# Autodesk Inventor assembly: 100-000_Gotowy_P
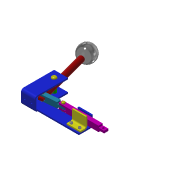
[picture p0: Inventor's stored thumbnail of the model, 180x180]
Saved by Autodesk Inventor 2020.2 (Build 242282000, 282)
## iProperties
Created: 2014-01
Part Number: 100-000_Gotowy_P
Document SubType Name: Assembly
Designer: F.Stasiak
Manager: www.cadconsulting.pl
Company: Fabian Stasiak CAD Consulting
Author: F.Stasiak
Subject: Zbiór ćwiczeń. Autodesk Inventor 2020. Kurs podstawowy
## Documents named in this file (11)
- C:\2020_Kurs_podstawowy\R6 Zespoły\Warsztat\Gotowe\100-000_Gotowy_P.iam
- C:\2020_Kurs_podstawowy\R6 Zespoły\Warsztat\Komponenty\100-002.ipt
- C:\2020_Kurs_podstawowy\R6 Zespoły\Warsztat\Komponenty\100-003.ipt
- C:\2020_Kurs_podstawowy\R6 Zespoły\Warsztat\Komponenty\100-004.ipt
- C:\2020_Kurs_podstawowy\R6 Zespoły\Warsztat\Komponenty\100-005.ipt
- C:\2020_Kurs_podstawowy\R6 Zespoły\Warsztat\Komponenty\100-006.ipt
- C:\2020_Kurs_podstawowy\R6 Zespoły\Warsztat\Komponenty\100-007.ipt
- C:\2020_Kurs_podstawowy\R6 Zespoły\Warsztat\Komponenty\100-008.ipt
- C:\2020_Kurs_podstawowy\R6 Zespoły\Warsztat\Komponenty\100-009.ipt
- C:\2020_Kurs_podstawowy\Zasoby\Content Center Files\pl-PL\ISO 4762(2)\ISO 4762 - M5 x 12ISO.ipt
- C:\2020_Kurs_podstawowy\R6 Zespoły\Warsztat\Komponenty\100-001G.ipt
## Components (13 placed, 10 different names)
1. 100-001G:1 — Obrotowe:1, Obrotowe:2, Obrotowe:4, Płaskie:1, Płaskie:3, Płaskie:4
2. 100-002:1 — Obrotowe:3, NAPĘD, Sztywne:3
3. 100-003:1 — Obrotowe:1
4. 100-003:2 — Obrotowe:2, Obrotowe:3
5. 100-004:1 — Obrotowe:4
6. 100-005:1 — NAPĘD, Obrotowe:6, Obrotowe:8
7. 100-006:1 — Płaskie:1, Obrotowe:6, Obrotowe:7, Płaskie:2
8. 100-007:1 — Płaskie:2, Płaskie:3, Płaskie:4, Sztywne:1, Sztywne:2
9. 100-008:1 — Sztywne:3
10. 100-009:1 — Obrotowe:7
11. 100-009:2 — Obrotowe:8
12. ISO 4762 M5 x 12:1 — Sztywne:2
13. ISO 4762 M5 x 12:2 — Sztywne:1
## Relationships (15: RevoluteJoint 8, PlanarJoint 4, WeldJoint 3)
- NAPĘD [RevoluteJoint]: 100-002:1 ↔ 100-005:1
- Obrotowe:1 [RevoluteJoint]: 100-001G:1 ↔ 100-003:1
- Obrotowe:2 [RevoluteJoint]: 100-001G:1 ↔ 100-003:2
- Obrotowe:3 [RevoluteJoint]: 100-002:1 ↔ 100-003:2
- Obrotowe:4 [RevoluteJoint]: 100-001G:1 ↔ 100-004:1
- Płaskie:1 [PlanarJoint]: 100-001G:1 ↔ 100-006:1
- Obrotowe:6 [RevoluteJoint]: 100-005:1 ↔ 100-006:1
- Obrotowe:7 [RevoluteJoint]: 100-006:1 ↔ 100-009:1
- Obrotowe:8 [RevoluteJoint]: 100-005:1 ↔ 100-009:2
- Płaskie:2 [PlanarJoint]: 100-006:1 ↔ 100-007:1
- Płaskie:3 [PlanarJoint]: 100-001G:1 ↔ 100-007:1
- Płaskie:4 [PlanarJoint]: 100-001G:1 ↔ 100-007:1
- Sztywne:1 [WeldJoint]: 100-007:1 ↔ ISO 4762 M5 x 12:2
- Sztywne:2 [WeldJoint]: 100-007:1 ↔ ISO 4762 M5 x 12:1
- Sztywne:3 [WeldJoint]: 100-002:1 ↔ 100-008:1
